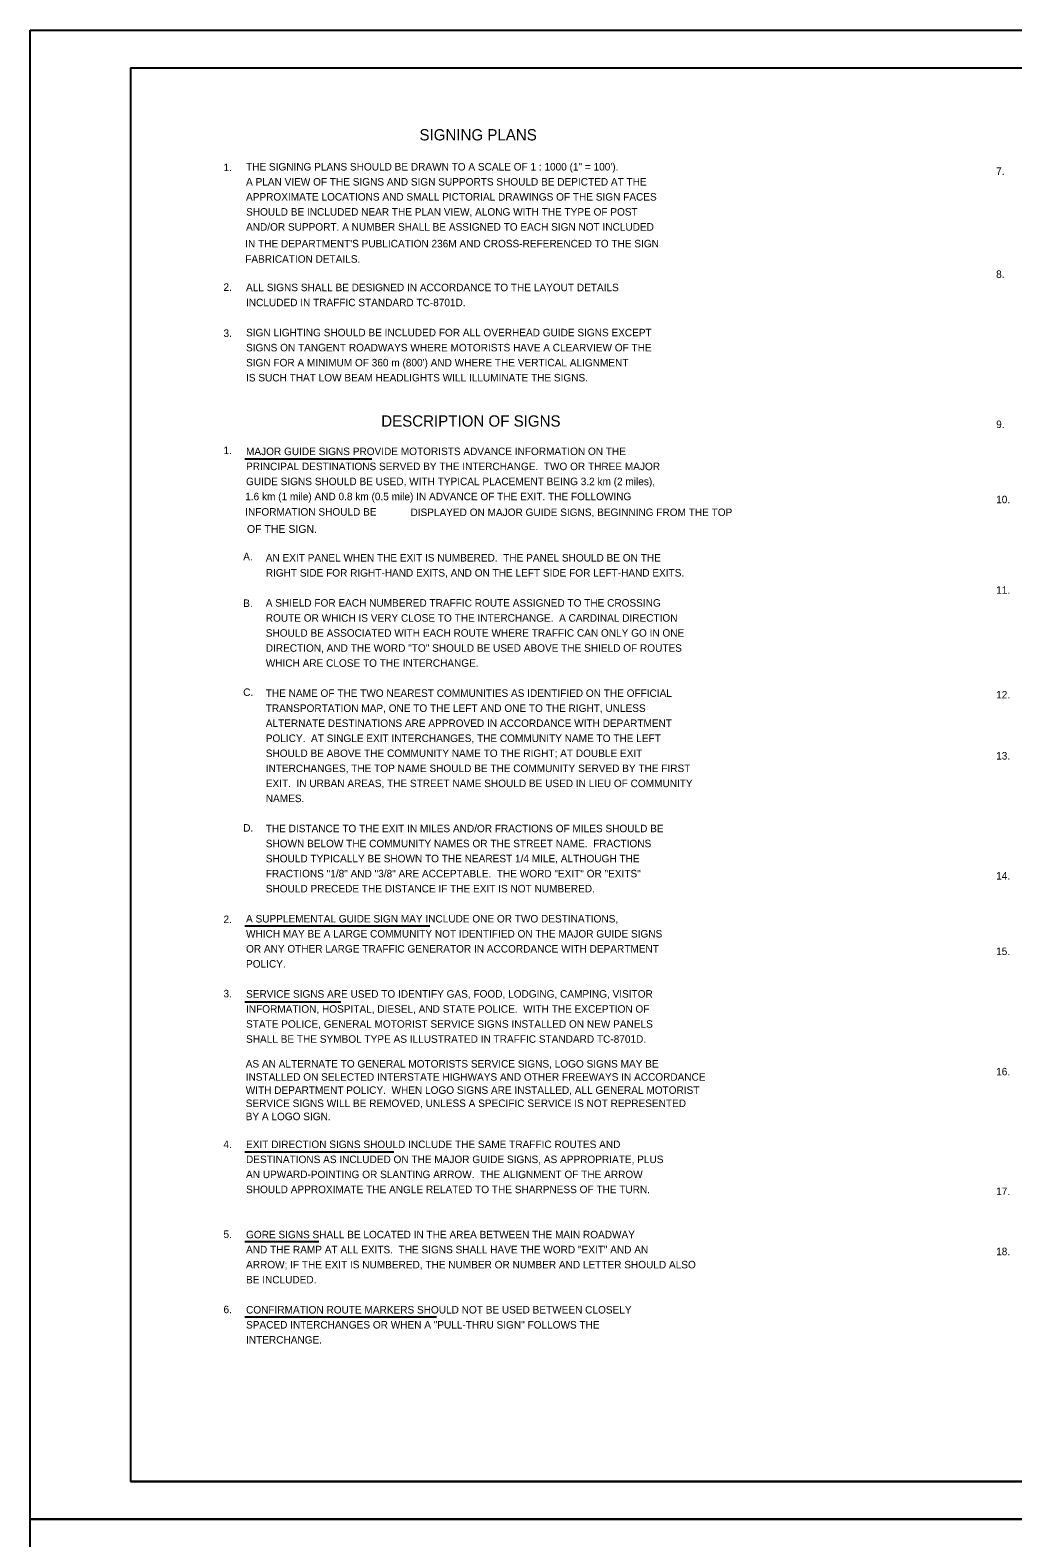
# Model space of a CAD drawing. Extents: x 640994 to 644422, y 298458 to 299646.
# Drawn here: x 640994 to 641386, y 299044 to 299646 of the extents above; entities that cross this region are included whole.
import ezdxf

# ---------------------------------------------------------------- set-up
doc = ezdxf.new("R2010")
doc.units = 0
for name, color, linetype in [('1', 7, 'Continuous'), ('2', 7, 'Continuous'), ('XCS-GRID-MIN', 7, 'Continuous')]:
    doc.layers.add(name, color=color, linetype=linetype)

msp = doc.modelspace()

# ---------------------------------------------------------------- linework, layer by layer
at = {"layer": '1'}
for p, q in [((641034.31, 299630.63), (641820.31, 299630.63)), ((641034.31, 299630.63), (641034.31, 299066.63)), ((641820.31, 299066.63), (641034.31, 299066.63)), ((641034.31, 299066.63), (641620.31, 299066.63))]:
    msp.add_line(p, q, dxfattribs=at)
at = {"layer": '2'}
for p, q in [((641079.94, 299474.59), (641130.56, 299474.59)), ((641079.94, 299288.25), (641153.81, 299288.25)), ((641079.94, 299258), (641118.31, 299258)), ((641079.94, 299198.13), (641139.44, 299198.13)), ((641079.94, 299162.38), (641109.44, 299162.38)), ((641079.94, 299132.25), (641156.44, 299132.25))]:
    msp.add_line(p, q, dxfattribs=at)
at = {"layer": 'XCS-GRID-MIN'}
for points in [[(640994.31, 299645.63), (641835.31, 299645.63), (641835.31, 299051.63), (640994.31, 299051.63)], [(640994.31, 299051.63), (641835.31, 299051.63), (641835.31, 298457.63), (640994.31, 298457.63)]]:
    msp.add_lwpolyline(points, close=True, dxfattribs=at)

# ---------------------------------------------------------------- texts
at = {"layer": '2'}
for s, height, p in [('SIGNING PLANS', 4.5, (641149.63, 299601.63)), ('1. ', 3, (641071.44, 299589.38)), ('THE SIGNING PLANS SHOULD BE DRAWN TO A SCALE OF 1 : 1000 (1" = 100\').', 3, (641080.44, 299589.63)), ('7.   ', 3, (641379.69, 299587.88)), ('A PLAN VIEW OF THE SIGNS AND SIGN SUPPORTS SHOULD BE DEPICTED AT THE ', 3, (641080.44, 299583.63)), ('APPROXIMATE LOCATIONS AND SMALL PICTORIAL DRAWINGS OF THE SIGN FACES ', 3, (641080.44, 299577.63)), ('SHOULD BE INCLUDED NEAR THE PLAN VIEW, ALONG WITH THE TYPE OF POST', 3, (641080.44, 299571.63)), ('AND/OR SUPPORT. A NUMBER SHALL BE ASSIGNED TO EACH SIGN NOT INCLUDED ', 3, (641080.44, 299565.63)), ("IN THE DEPARTMENT'S PUBLICATION 236M AND CROSS-REFERENCED TO THE SIGN", 3, (641080.11, 299558.97)), ('FABRICATION DETAILS.', 3, (641080.11, 299552.84)), ('8.   ', 3, (641379.69, 299546.75)), ('2.   ', 3, (641071.44, 299541.61)), ('ALL SIGNS SHALL BE DESIGNED IN ACCORDANCE TO THE LAYOUT DETAILS', 3, (641080.44, 299541.48)), ('INCLUDED IN TRAFFIC STANDARD TC-8701D.', 3, (641080.44, 299535.48)), ('3.   ', 3, (641071.44, 299523.23)), ('SIGN LIGHTING SHOULD BE INCLUDED FOR ALL OVERHEAD GUIDE SIGNS EXCEPT', 3, (641080.44, 299523.48)), ('SIGNS ON TANGENT ROADWAYS WHERE MOTORISTS HAVE A CLEARVIEW OF THE', 3, (641080.44, 299517.48)), ("SIGN FOR A MINIMUM OF 360 m (800') AND WHERE THE VERTICAL ALIGNMENT ", 3, (641080.44, 299511.48)), ('IS SUCH THAT LOW BEAM HEADLIGHTS WILL ILLUMINATE THE SIGNS.', 3, (641080.44, 299505.48)), ('DESCRIPTION OF SIGNS', 4.5, (641134.37, 299487.45)), ('9.   ', 3, (641379.69, 299486.88)), ('1.  ', 3, (641071.44, 299476.47)), ('MAJOR GUIDE SIGNS PROVIDE MOTORISTS ADVANCE INFORMATION ON THE', 3, (641080.44, 299476.09)), ('PRINCIPAL DESTINATIONS SERVED BY THE INTERCHANGE.  TWO OR THREE MAJOR', 3, (641080.44, 299470.09)), ('GUIDE SIGNS SHOULD BE USED, WITH TYPICAL PLACEMENT BEING 3.2 km (2 miles),', 3, (641080.44, 299464.09)), ('1.6 km (1 mile) AND 0.8 km (0.5 mile) IN ADVANCE OF THE EXIT. THE FOLLOWING', 3, (641080.11, 299458.08)), ('10.', 3, (641379.69, 299456.88)), ('INFORMATION SHOULD BE', 3, (641080.11, 299451.95)), ('DISPLAYED ON MAJOR GUIDE SIGNS, BEGINNING FROM THE TOP', 3, (641146.04, 299451.77)), ('OF THE SIGN.', 3.1343, (641080.8, 299445.07)), ('A. ', 3, (641079.31, 299434.13)), ('AN EXIT PANEL WHEN THE EXIT IS NUMBERED.  THE PANEL SHOULD BE ON THE', 3, (641088.31, 299433.63)), ('RIGHT SIDE FOR RIGHT-HAND EXITS, AND ON THE LEFT SIDE FOR LEFT-HAND EXITS.', 3, (641088.31, 299427.63)), ('11.', 3, (641379.69, 299420.75)), ('B.  ', 3, (641079.31, 299415.5)), ('A SHIELD FOR EACH NUMBERED TRAFFIC ROUTE ASSIGNED TO THE CROSSING', 3, (641088.31, 299415.63)), ('ROUTE OR WHICH IS VERY CLOSE TO THE INTERCHANGE.  A CARDINAL DIRECTION', 3, (641088.31, 299409.63)), ('SHOULD BE ASSOCIATED WITH EACH ROUTE WHERE TRAFFIC CAN ONLY GO IN ONE', 3, (641088.31, 299403.63)), ('DIRECTION, AND THE WORD "TO" SHOULD BE USED ABOVE THE SHIELD OF ROUTES', 3, (641088.31, 299397.63)), ('WHICH ARE CLOSE TO THE INTERCHANGE.', 3, (641088.31, 299391.63)), ('C.   ', 3, (641079.31, 299380)), ('THE NAME OF THE TWO NEAREST COMMUNITIES AS IDENTIFIED ON THE OFFICIAL', 3, (641088.31, 299379.63)), ('12.', 3, (641379.69, 299379)), ('TRANSPORTATION MAP, ONE TO THE LEFT AND ONE TO THE RIGHT, UNLESS', 3, (641088.31, 299373.63)), ('ALTERNATE DESTINATIONS ARE APPROVED IN ACCORDANCE WITH DEPARTMENT', 3, (641088.31, 299367.63)), ('POLICY.  AT SINGLE EXIT INTERCHANGES, THE COMMUNITY NAME TO THE LEFT', 3, (641088.31, 299361.63)), ('SHOULD BE ABOVE THE COMMUNITY NAME TO THE RIGHT; AT DOUBLE EXIT', 3, (641088.31, 299355.63)), ('13.', 3, (641379.69, 299354.63)), ('INTERCHANGES, THE TOP NAME SHOULD BE THE COMMUNITY SERVED BY THE FIRST', 3, (641088.31, 299349.63)), ('EXIT.  IN URBAN AREAS, THE STREET NAME SHOULD BE USED IN LIEU OF COMMUNITY', 3, (641088.31, 299343.63)), ('NAMES.', 3, (641088.31, 299337.63)), ('D.   ', 3, (641079.31, 299325.88)), ('THE DISTANCE TO THE EXIT IN MILES AND/OR FRACTIONS OF MILES SHOULD BE', 3, (641088.31, 299325.63)), ('SHOWN BELOW THE COMMUNITY NAMES OR THE STREET NAME.  FRACTIONS', 3, (641088.31, 299319.63)), ('SHOULD TYPICALLY BE SHOWN TO THE NEAREST 1/4 MILE, ALTHOUGH THE', 3, (641088.31, 299313.63)), ('FRACTIONS "1/8" AND "3/8" ARE ACCEPTABLE.  THE WORD "EXIT" OR "EXITS"', 3, (641088.31, 299307.63)), ('14.', 3, (641379.69, 299306.75)), ('SHOULD PRECEDE THE DISTANCE IF THE EXIT IS NOT NUMBERED.', 3, (641088.31, 299301.63)), ('2.  ', 3, (641071.44, 299289.38)), ('A SUPPLEMENTAL GUIDE SIGN MAY INCLUDE ONE OR TWO DESTINATIONS,', 3, (641080.44, 299289.63)), ('WHICH MAY BE A LARGE COMMUNITY NOT IDENTIFIED ON THE MAJOR GUIDE SIGNS', 3, (641080.44, 299283.63)), ('OR ANY OTHER LARGE TRAFFIC GENERATOR IN ACCORDANCE WITH DEPARTMENT', 3, (641080.44, 299277.63)), ('15.', 3, (641379.69, 299276.63)), ('POLICY.', 3, (641080.44, 299271.63)), ('3.  ', 3, (641071.44, 299259.75)), ('SERVICE SIGNS ARE USED TO IDENTIFY GAS, FOOD, LODGING, CAMPING, VISITOR', 3, (641080.44, 299259.63)), ('INFORMATION, HOSPITAL, DIESEL, AND STATE POLICE.  WITH THE EXCEPTION OF', 3, (641080.44, 299253.63)), ('STATE POLICE, GENERAL MOTORIST SERVICE SIGNS INSTALLED ON NEW PANELS', 3, (641080.44, 299247.63)), ('SHALL BE THE SYMBOL TYPE AS ILLUSTRATED IN TRAFFIC STANDARD TC-8701D.', 3, (641080.44, 299241.63)), ('AS AN ALTERNATE TO GENERAL MOTORISTS SERVICE SIGNS, LOGO SIGNS MAY BE', 3, (641080.31, 299231.75)), ('INSTALLED ON SELECTED INTERSTATE HIGHWAYS AND OTHER FREEWAYS IN ACCORDANCE', 3, (641080.31, 299226.5)), ('16.   ', 3, (641379.69, 299228.63)), ('WITH DEPARTMENT POLICY.  WHEN LOGO SIGNS ARE INSTALLED, ALL GENERAL MOTORIST', 3, (641080.31, 299221.25)), ('SERVICE SIGNS WILL BE REMOVED, UNLESS A SPECIFIC SERVICE IS NOT REPRESENTED', 3, (641080.31, 299216)), ('BY A LOGO SIGN.', 3, (641080.31, 299210.75)), ('4.  ', 3, (641071.44, 299199.63)), ('EXIT DIRECTION SIGNS SHOULD INCLUDE THE SAME TRAFFIC ROUTES AND', 3, (641080.44, 299199.63)), ('DESTINATIONS AS INCLUDED ON THE MAJOR GUIDE SIGNS, AS APPROPRIATE, PLUS', 3, (641080.44, 299193.63)), ('AN UPWARD-POINTING OR SLANTING ARROW.  THE ALIGNMENT OF THE ARROW', 3, (641080.44, 299187.63)), ('SHOULD APPROXIMATE THE ANGLE RELATED TO THE SHARPNESS OF THE TURN.', 3, (641080.44, 299181.63)), ('17.   ', 3, (641379.69, 299180.88)), ('5.  ', 3, (641071.44, 299163.75)), ('GORE SIGNS SHALL BE LOCATED IN THE AREA BETWEEN THE MAIN ROADWAY', 3, (641080.44, 299163.63)), ('AND THE RAMP AT ALL EXITS.  THE SIGNS SHALL HAVE THE WORD "EXIT" AND AN', 3, (641080.44, 299157.63)), ('18.', 3, (641379.69, 299156.88)), ('ARROW; IF THE EXIT IS NUMBERED, THE NUMBER OR NUMBER AND LETTER SHOULD ALSO', 3, (641080.44, 299151.63)), ('BE INCLUDED.', 3, (641080.44, 299145.63)), ('6. ', 3, (641071.44, 299133.75)), ('CONFIRMATION ROUTE MARKERS SHOULD NOT BE USED BETWEEN CLOSELY', 3, (641080.44, 299133.63)), ('SPACED INTERCHANGES OR WHEN A "PULL-THRU SIGN" FOLLOWS THE', 3, (641080.44, 299127.63)), ('INTERCHANGE.', 3, (641080.44, 299121.63))]:
    msp.add_text(s, height=height, dxfattribs=at).set_placement(p)

doc.saveas('drawing.dxf')
